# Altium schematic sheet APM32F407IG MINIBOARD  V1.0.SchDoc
size A2; Organization: Altium Limited; Address1: 3 Minna Close; Address2: Belrose; Address3: NSW 2085; Address4: Australia; PageSetup: Record=PageOptions¦CenterHorizontal=True¦CenterVertical=True¦PrintScale=0.52¦XCorrection=1.00¦YCorrection=1.00¦PrintKind=0¦BorderSize=5000000¦LeftOffset=0¦BottomOffset=0¦Orientation=2¦PaperLength=1000¦PaperWidth=1000¦Scale=100¦PaperSource=7¦PrintQuality=-4¦MediaType=1¦DitherType=10¦PaperKind=A4¦PrintScaleMode=1
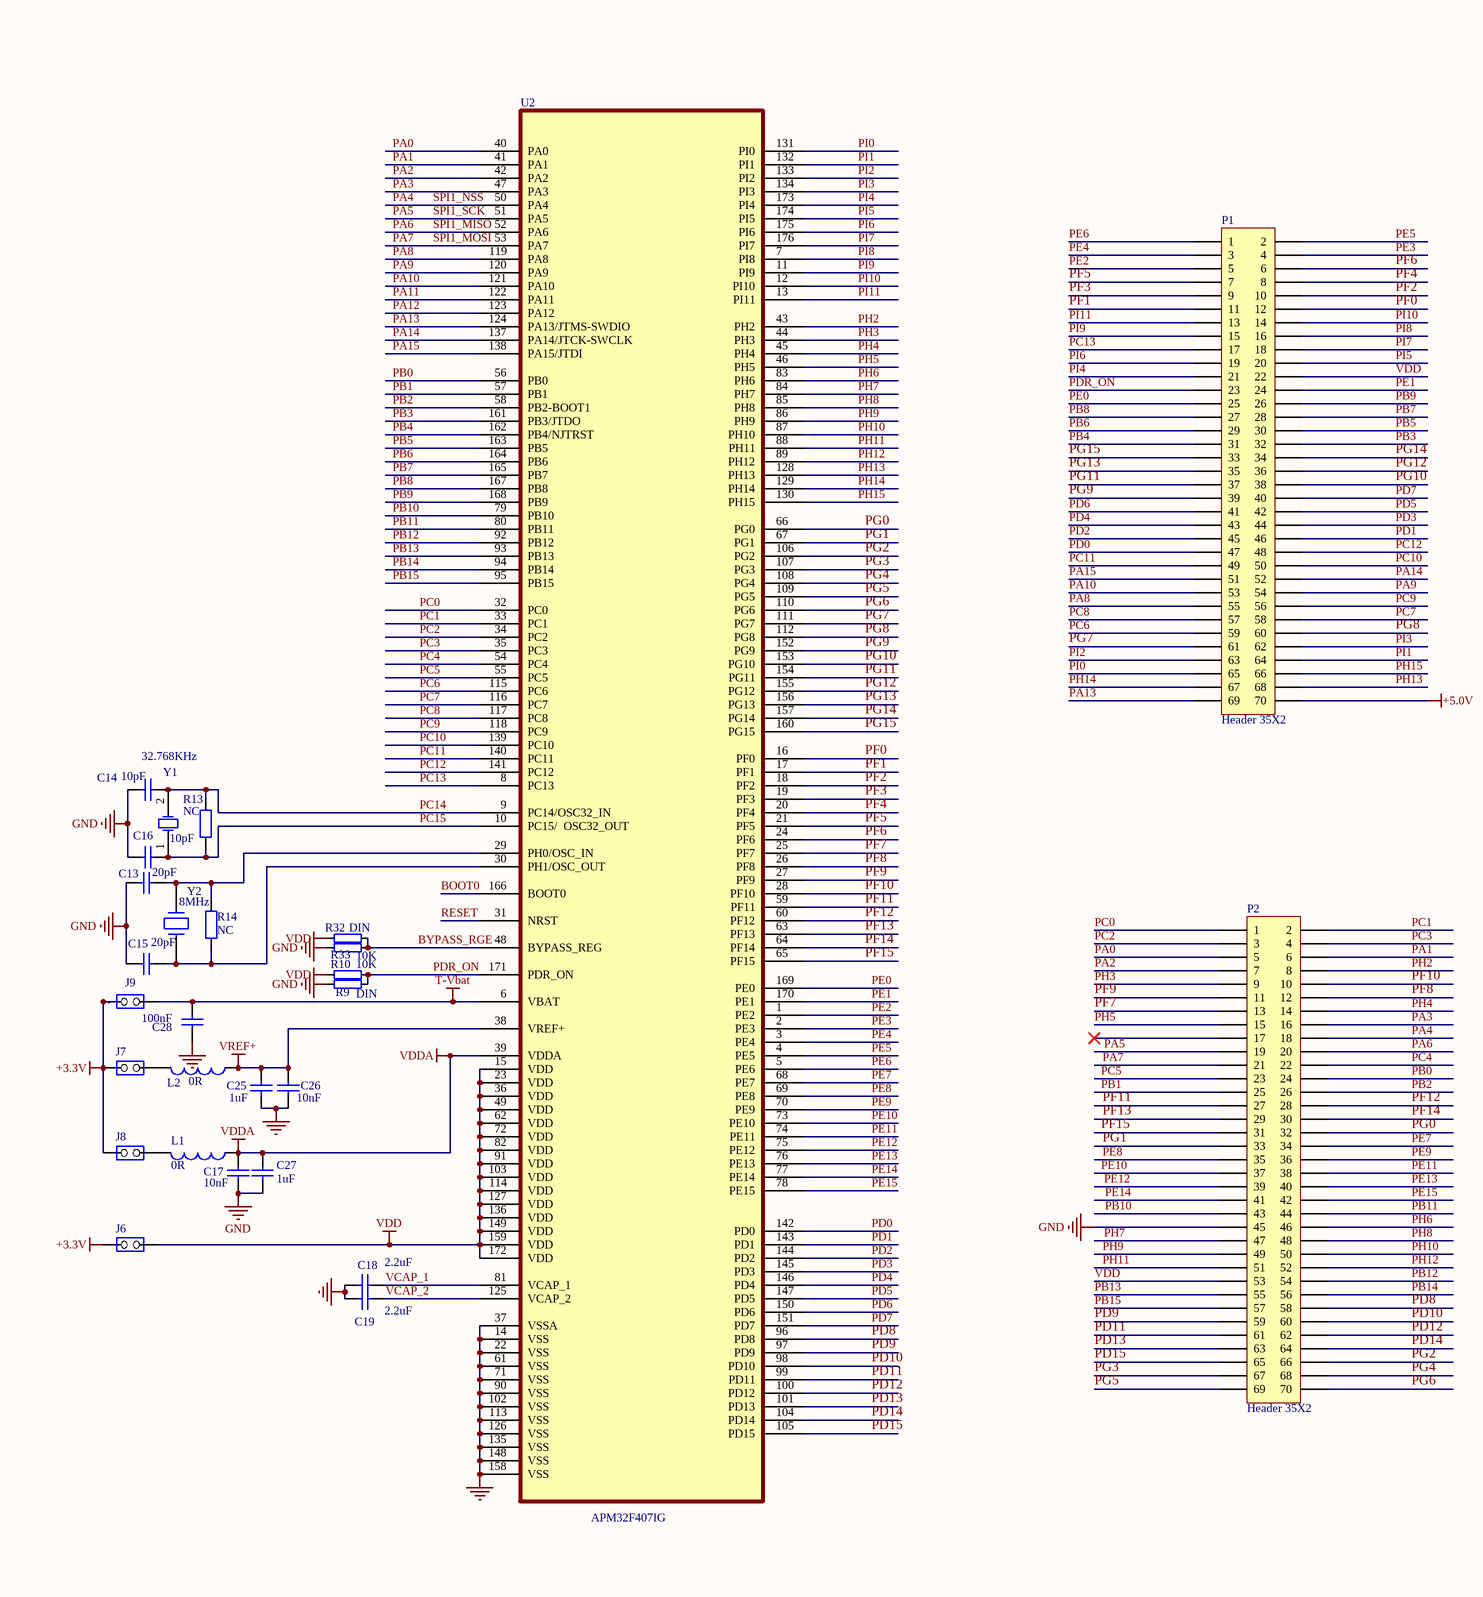
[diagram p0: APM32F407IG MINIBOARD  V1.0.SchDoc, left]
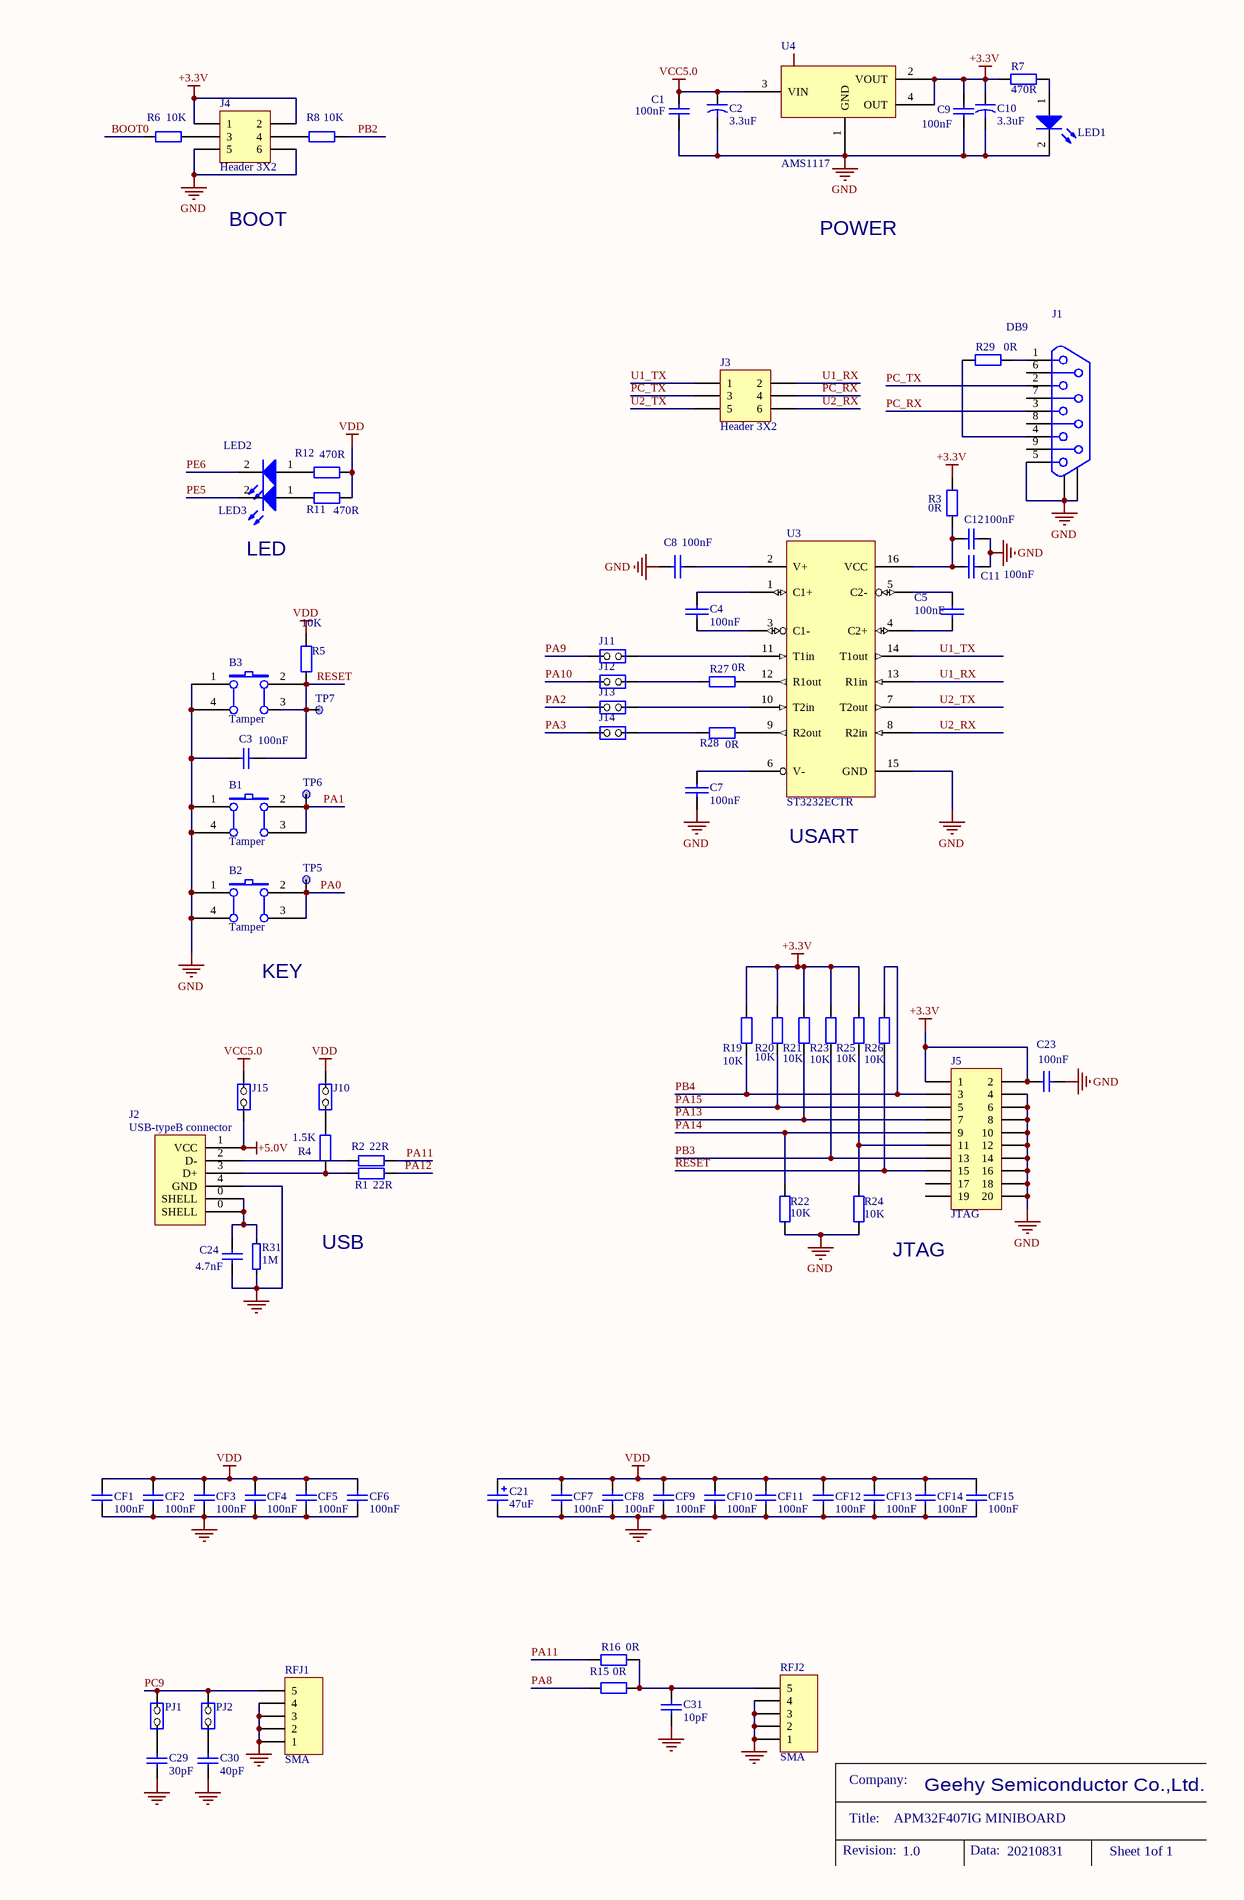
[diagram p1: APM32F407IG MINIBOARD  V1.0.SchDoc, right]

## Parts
B1  Tamper  [PB10]
B2  Tamper  [PB10]
B3  Tamper  [PB10]
C1  100nF  [0603P]
C2  3.3uF  [TAN-B]
C3  100nF  [0603P]
C4  100nF  [0603P]
C5  100nF  [0603P]
C7  100nF  [0603P]
C8  100nF  [0603P]
C9  100nF  [0603P]
C10  3.3uF  [TAN-B]
C11  100nF  [0603P]
C12  100nF  [0603P]
C13  10pF  [0603P]
C14  10pF  [0603P]
C15  20pF  [0603P]
C16  20pF  [0603P]
C17  10nF  [0603P]
C18  2.2uF  [0603P]
C19  2.2uF  [0603P]
C21  47uF  [TAN-B]
C23  100nF  [0603P]
C24  4.7nF  [0603]
C25  1uF  [0603P]
C26  10nF  [0603P]
C27  1uF  [0603P]
C28  100nF  [0603P]
C29  30pF  [0603P]
C30  40pF  [0603P]
C31  10pF  [0603P]
CF1  100nF  [0603P]
CF2  100nF  [0603P]
CF3  100nF  [0603P]
CF4  100nF  [0603P]
CF5  100nF  [0603P]
CF6  100nF  [0603P]
CF7  100nF  [0603P]
CF8  100nF  [0603P]
CF9  100nF  [0603P]
CF10  100nF  [0603P]
CF11  100nF  [0603P]
CF12  100nF  [0603P]
CF13  100nF  [0603P]
CF14  100nF  [0603P]
CF15  100nF  [0603P]
J1  DB9  [DB9/F]
J2  USB-typeB connector  [USB-B]
J3  Header 3X2  [HDR2X3]
J4  Header 3X2  [HDR2X3]
J5  JTAG  [IDC20S]
J6  (no value)  [SIP2]
J7  (no value)  [SIP2]
J8  (no value)  [SIP2]
J9  (no value)  [SIP2]
J10  (no value)  [SIP2]
J11  (no value)  [SIP2]
J12  (no value)  [SIP2]
J13  (no value)  [SIP2]
J14  (no value)  [SIP2]
J15  (no value)  [SIP2]
L1  0R  [0603]
L2  0R  [0603]
LED1  LED  [D0603]  (value not drawn)
LED2  LED  [D0603]  (value not drawn)
LED3  LED  [D0603]  (value not drawn)
P1  Header 35X2  [HDR2X35]
P2  Header 35X2  [HDR2X35]
PJ1  (no value)  [SIP2]
PJ2  (no value)  [SIP2]
R1  22R  [0603]
R2  22R  [0603]
R3  0R  [0603]
R4  1.5K  [0603]
R5  10K  [0603]
R6  10K  [0603]
R7  470R  [0603]
R8  10K  [0603]
R9  DIN  [0603]
R10  10K  [0603]
R11  470R  [0603]
R12  470R  [0603]
R13  NC  [0603]
R14  NC  [0603]
R15  0R  [0603]
R16  0R  [0603]
R19  10K  [0603]
R20  10K  [0603]
R21  10K  [0603]
R22  10K  [0603]
R23  10K  [0603]
R24  10K  [0603]
R25  10K  [0603]
R26  10K  [0603]
R27  0R  [0603]
R28  0R  [0603]
R29  0R  [0603]
R31  1M  [0603]
R32  DIN  [0603]
R33  10K  [0603]
RFJ1  SMA  [RFCON - SMA]
RFJ2  SMA  [RFCON - SMA]
TP5  (no value)  [TP1.5]
TP6  (no value)  [TP1.5]
TP7  (no value)  [TP1.5]
U2  APM32F407IG  [LQFP-176N]
U3  ST3232ECTR  [TSSOP16]
U4  AMS1117  [SPX1117M]
Y1  32.768KHz  [R1206]
Y2  8MHz  [XTAL_socket]

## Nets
+3.3V: C9.2 C10.1 C23.2 J4.1 J4.2 J5.1 J5.2 J6.1(COMMON) J7.1(COMMON) J8.1(COMMON) J9.1(COMMON) R3.2 R7.2 R19.2 R20.2 R21.2 R23.2 R25.2 U4.2(VOUT) U4.4(OUT)
+5.0V: J2.1(VCC) J15.2(NO) P1.70
GND: B1.1(A0) B1.4(A1) B2.1(A0) B2.4(A1) B3.1(A0) B3.4(A1) C1.1 C2.2 C3.1 C7.1 C8.1 C9.1 C10.2 C11.2 C12.1 C13.1 C14.1 C15.1 C16.1 C17.1 C18.1 C19.2 C21.2 C23.1 C24.1 C25.1 C26.1 C27.1 C28.1 C29.2 C30.2 C31.2 CF1.2 CF2.2 CF3.2 CF4.2 CF5.2 CF6.2 CF7.2 CF8.2 CF9.2 CF10.2 CF11.2 CF12.2 CF13.2 CF14.2 CF15.2 J1.0 J1.5 J2.4(GND) J4.5 J4.6 J5.4 J5.6 J5.8 J5.10 J5.12 J5.14 J5.16 J5.18 J5.20 LED1.2(K) P2.45 R9.1 R22.1 R24.1 R31.1 R33.1 RFJ1.1 RFJ1.2 RFJ1.3 RFJ1.4 RFJ2.1 RFJ2.2 RFJ2.3 RFJ2.4 U2.14(VSS) U2.22(VSS) U2.37(VSSA) U2.61(VSS) U2.71(VSS) U2.90(VSS) U2.102(VSS) U2.113(VSS) U2.126(VSS) U2.135(VSS) U2.148(VSS) U2.158(VSS) U3.15(GND) U4.1(GND)
T-Vbat: C28.2 J9.2(NO) U2.6(VBAT)
VCC5.0: C1.2 C2.1 J15.1(COMMON) U4.3(VIN)
VDD: C21.1 CF1.1 CF2.1 CF3.1 CF4.1 CF5.1 CF6.1 CF7.1 CF8.1 CF9.1 CF10.1 CF11.1 CF12.1 CF13.1 CF14.1 CF15.1 J6.2(NO) J10.1(COMMON) P1.22 P2.53 R5.1 R10.2 R11.1 R12.1 R32.2 U2.15(VDD) U2.23(VDD) U2.36(VDD) U2.49(VDD) U2.62(VDD) U2.72(VDD) U2.82(VDD) U2.91(VDD) U2.103(VDD) U2.114(VDD) U2.127(VDD) U2.136(VDD) U2.149(VDD) U2.159(VDD) U2.172(VDD)
VDDA: C17.2 C27.2 L1.1 U2.39(VDDA)
VREF+: C25.2 C26.2 L2.1 U2.38(VREF+)
BOOT0: R6.1 U2.166(BOOT0)
BYPASS_RGE: R32.1 R33.2 U2.48(BYPASS_REG)
PA0: B2.2(B0) B2.3(B1) P2.5 TP5.1 U2.40(PA0)
PA1: B1.2(B0) B1.3(B1) P2.6 TP6.1 U2.41(PA1)
PA2: J13.2(NO) P2.7 U2.42(PA2)
PA3: J14.2(NO) P2.16 U2.47(PA3)
PA4: P2.18 U2.50(PA4)  [also labelled SPI1_NSS]
PA5: P2.19 U2.51(PA5)  [also labelled SPI1_SCK]
PA6: P2.20 U2.52(PA6)  [also labelled SPI1_MISO]
PA7: P2.21 U2.53(PA7)  [also labelled SPI1_MOSI]
PA8: P1.55 R15.1 U2.119(PA8)
PA9: J11.2(NO) P1.54 U2.120(PA9)
PA10: J12.2(NO) P1.53 U2.121(PA10)
PA11: R2.2 R16.2 U2.122(PA11)
PA12: R1.2 U2.123(PA12)
PA13: J5.7 P1.69 R21.1 U2.124(PA13/JTMS-SWDIO)
PA14: J5.9 P1.52 R22.2 U2.137(PA14/JTCK-SWCLK)
PA15: J5.5 P1.51 R20.1 U2.138(PA15/JTDI)
PB0: P2.24 U2.56(PB0)
PB1: P2.25 U2.57(PB1)
PB2: P2.26 R8.2 U2.58(PB2-BOOT1)
PB3: J5.13 P1.32 R23.1 U2.161(PB3/JTDO)
PB4: J5.3 P1.31 R19.1 R26.2 U2.162(PB4/NJTRST)
PB5: P1.30 U2.163(PB5)
PB6: P1.29 U2.164(PB6)
PB7: P1.28 U2.165(PB7)
PB8: P1.27 U2.167(PB8)
PB9: P1.26 U2.168(PB9)
PB10: P2.43 U2.79(PB10)
PB11: P2.44 U2.80(PB11)
PB12: P2.54 U2.92(PB12)
PB13: P2.55 U2.93(PB13)
PB14: P2.56 U2.94(PB14)
PB15: P2.57 U2.95(PB15)
PC0: P2.1 U2.32(PC0)
PC1: P2.2 U2.33(PC1)
PC2: P2.3 U2.34(PC2)
PC3: P2.4 U2.35(PC3)
PC4: P2.22 U2.54(PC4)
PC5: P2.23 U2.55(PC5)
PC6: P1.59 U2.115(PC6)
PC7: P1.58 U2.116(PC7)
PC8: P1.57 U2.117(PC8)
PC9: P1.56 PJ1.2(NO) PJ2.2(NO) RFJ1.5 U2.118(PC9)
PC10: P1.50 U2.139(PC10)
PC11: P1.49 U2.140(PC11)
PC12: P1.48 U2.141(PC12)
PC13: P1.17 U2.8(PC13)
PC14: C14.2 R13.1 U2.9(PC14/OSC32_IN) Y1.2(OSC2)
PC15: C13.2 R13.2 U2.10(PC15/__OSC32_OUT) Y1.1(OSC1)
PC_RX: J1.3 J3.4
PC_TX: J1.2 J3.3
PD0: P1.47 U2.142(PD0)
PD1: P1.46 U2.143(PD1)
PD2: P1.45 U2.144(PD2)
PD3: P1.44 U2.145(PD3)
PD4: P1.43 U2.146(PD4)
PD5: P1.42 U2.147(PD5)
PD6: P1.41 U2.150(PD6)
PD7: P1.40 U2.151(PD7)
PD8: P2.58 U2.96(PD8)
PD9: P2.59 U2.97(PD9)
PD10: P2.60 U2.98(PD10)
PD11: P2.61 U2.99(PD11)
PD12: P2.62 U2.100(PD12)
PD13: P2.63 U2.101(PD13)
PD14: P2.64 U2.104(PD14)
PD15: P2.65 U2.105(PD15)
PDR_ON: P1.23 R9.2 R10.1 U2.171(PDR_ON)
PE0: P1.25 U2.169(PE0)
PE1: P1.24 U2.170(PE1)
PE2: P1.5 U2.1(PE2)
PE3: P1.4 U2.2(PE3)
PE4: P1.3 U2.3(PE4)
PE5: LED3.2(K) P1.2 U2.4(PE5)
PE6: LED2.2(K) P1.1 U2.5(PE6)
PE7: P2.34 U2.68(PE7)
PE8: P2.35 U2.69(PE8)
PE9: P2.36 U2.70(PE9)
PE10: P2.37 U2.73(PE10)
PE11: P2.38 U2.74(PE11)
PE12: P2.39 U2.75(PE12)
PE13: P2.40 U2.76(PE13)
PE14: P2.41 U2.77(PE14)
PE15: P2.42 U2.78(PE15)
PF0: P1.12 U2.16(PF0)
PF1: P1.11 U2.17(PF1)
PF2: P1.10 U2.18(PF2)
PF3: P1.9 U2.19(PF3)
PF4: P1.8 U2.20(PF4)
PF5: P1.7 U2.21(PF5)
PF6: P1.6 U2.24(PF6)
PF7: P2.13 U2.25(PF7)
PF8: P2.12 U2.26(PF8)
PF9: P2.11 U2.27(PF9)
PF10: P2.10 U2.28(PF10)
PF11: P2.27 U2.59(PF11)
PF12: P2.28 U2.60(PF12)
PF13: P2.29 U2.63(PF13)
PF14: P2.30 U2.64(PF14)
PF15: P2.31 U2.65(PF15)
PG0: P2.32 U2.66(PG0)
PG1: P2.33 U2.67(PG1)
PG2: P2.66 U2.106(PG2)
PG3: P2.67 U2.107(PG3)
PG4: P2.68 U2.108(PG4)
PG5: P2.69 U2.109(PG5)
PG6: P2.70 U2.110(PG6)
PG7: P1.61 U2.111(PG7)
PG8: P1.60 U2.112(PG8)
PG9: P1.39 U2.152(PG9)
PG10: P1.38 U2.153(PG10)
PG11: P1.37 U2.154(PG11)
PG12: P1.36 U2.155(PG12)
PG13: P1.35 U2.156(PG13)
PG14: P1.34 U2.157(PG14)
PG15: P1.33 U2.160(PG15)
PH2: P2.8 U2.43(PH2)
PH3: P2.9 U2.44(PH3)
PH4: P2.14 U2.45(PH4)
PH5: P2.15 U2.46(PH5)
PH6: P2.46 U2.83(PH6)
PH7: P2.47 U2.84(PH7)
PH8: P2.48 U2.85(PH8)
PH9: P2.49 U2.86(PH9)
PH10: P2.50 U2.87(PH10)
PH11: P2.51 U2.88(PH11)
PH12: P2.52 U2.89(PH12)
PH13: P1.68 U2.128(PH13)
PH14: P1.67 U2.129(PH14)
PH15: P1.66 U2.130(PH15)
PI0: P1.65 U2.131(PI0)
PI1: P1.64 U2.132(PI1)
PI2: P1.63 U2.133(PI2)
PI3: P1.62 U2.134(PI3)
PI4: P1.21 U2.173(PI4)
PI5: P1.20 U2.174(PI5)
PI6: P1.19 U2.175(PI6)
PI7: P1.18 U2.176(PI7)
PI8: P1.16 U2.7(PI8)
PI9: P1.15 U2.11(PI9)
PI10: P1.14 U2.12(PI10)
PI11: P1.13 U2.13(PI11)
RESET: B3.2(B0) B3.3(B1) C3.2 J5.15 R5.2 R26.1 TP7.1 U2.31(NRST)
U1_RX: J3.2 U3.13(R1in)
U1_TX: J3.1 U3.14(T1out)
U2_RX: J3.6 U3.8(R2in)
U2_TX: J3.5 U3.7(T2out)
VCAP_1: C18.2 U2.81(VCAP_1)
VCAP_2: C19.1 U2.125(VCAP_2)
NetC4_1: C4.1 U3.1(C1+)
NetC4_2: C4.2 U3.3(C1-)
NetC5_1: C5.1 U3.4(C2+)
NetC5_2: C5.2 U3.5(C2-)
NetC7_2: C7.2 U3.6(V-)
NetC8_2: C8.2 U3.2(V+)
NetC11_1: C11.1 C12.2 R3.1 U3.16(VCC)
NetC15_2: C15.2 R14.2 U2.30(PH1/OSC_OUT) Y2.1
NetC16_2: C16.2 R14.1 U2.29(PH0/OSC_IN) Y2.2
NetC24_2: C24.2 J2.0(SHELL) R31.2
NetC29_1: C29.1 PJ1.1(COMMON)
NetC30_1: C30.1 PJ2.1(COMMON)
NetC31_1: C31.1 R15.2 R16.1 RFJ2.5
NetJ1_1: J1.1 R29.2
NetJ1_4: J1.4 R29.1
NetJ2_2: J2.2(D-) R2.1
NetJ2_3: J2.3(D+) R1.1 R4.1
NetJ4_3: J4.3 R6.2
NetJ4_4: J4.4 R8.1
NetJ5_11: J5.11 R24.2 R25.1
NetJ7_2: J7.2(NO) L2.2
NetJ8_2: J8.2(NO) L1.2
NetJ10_2: J10.2(NO) R4.2
NetJ11_1: J11.1(COMMON) U3.11(T1in)
NetJ12_1: J12.1(COMMON) R27.1
NetJ13_1: J13.1(COMMON) U3.10(T2in)
NetJ14_1: J14.1(COMMON) R28.1
NetLED1_1: LED1.1(A) R7.1
NetLED2_1: LED2.1(A) R12.2
NetLED3_1: LED3.1(A) R11.2
NetR27_2: R27.2 U3.12(R1out)
NetR28_2: R28.2 U3.9(R2out)

Not connected (* = marked no-connect by the designer): J1 6 7 8 9; J5 17 19; P2 17*

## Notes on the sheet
- BOOT
- POWER
- LED
- USART
- (near B2) KEY
- USB
- JTAG
- Company:
- Geehy Semiconductor Co.,Ltd.
- Revision:
- Title:
- APM32F407IG MINIBOARD
- 1.0
- Data:
- 20210831
- Sheet 1of 1

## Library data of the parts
B1-B3 = SW PUSHBUTTON: SE PUSHBUTTON
C1 C3 C9 C12 C17-C19 C23 C25-C28 = Cap: Capacitor; Value: 104
C2 C10 = Cap2: Capacitor; Value: 220uF
C4 C5 C7 C8 C11 CF1-CF15 = CAP: Capacitor
C13-C16 = Cap: Capacitor
C21 = Cap Pol1: Polarized Capacitor (Radial); Value: 100pF
C24 = CAP: Capacitor; Value: 100pF
C29-C31 = Cap: Capacitor; Value: 10nF
J2 = USB-B
J3 J4 = Header 3X2: Header, 3-Pin, Dual row
J5 = Header 10X2: Header, 10-Pin, Dual row
J6-J15 PJ1 PJ2 = JP2
L1 L2 = Inductor: Value: 100uH
LED1-LED3 = LED2: Typical RED, GREEN, YELLOW, AMBER GaAs LED
P1 P2 = Header 35X2: Header, 30-Pin, Dual row
R1 R4-R6 R8 R19-R26 = Res2: Resistor
R2 = Res2: Resistor; Value: 20
R3 R15 R16 R27-R29 = Res2: Resistor; Value: 1K
R7 R11 R12 = Res2: Resistor; Value: 470
R9 R10 R31-R33 = RES: '1/8W 5%; 描述: 5%/1/10W
R13 = Res2: Resistor; Value: 4.7K
R14 = Res2: Resistor; Value: 1M
RFJ1 RFJ2 = Header 5: Header, 5-Pin
TP5-TP7 = TP
U3 = ST3232: 3.3V/5V Dual RS232 Transceiver w/ Int. Cap.
U4 = SPX1117
Y1 = XTAL: Crystal Oscillator
Y2 = CRYSTAL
